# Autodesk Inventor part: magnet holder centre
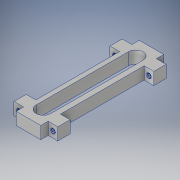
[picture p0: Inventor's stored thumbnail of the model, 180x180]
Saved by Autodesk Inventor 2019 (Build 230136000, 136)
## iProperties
Created: 2019-05
Part Number: magnet holder centre
Material: Aluminum 6061
Document SubType Name: Modeling
Designer: Chloe
Density: 2.7 g/cm^3
Appearance: Aluminum - Flat
Author: Chloe
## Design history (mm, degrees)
sketch "Sketch1"
  geometry: L1 (0, 0)-(-20, 0); L2 (-20, 0)-(-20, -100); L3 (-20, -100)-(0, -100); L4 (0, -100)-(0, 0); L5 (0, -6)-(7.831, -6); L6 (7.831, -6)-(7.831, -16); L7 (7.831, -16)-(0, -16); L8 (0, -16)-(0, -6); L9 (-20, -6)-(-27.831, -6); L10 (-27.831, -6)-(-27.831, -16); L11 (-27.831, -16)-(-20, -16); L12 (-20, -16)-(-20, -6); L13 (-20, -84)-(-27.831, -84); L14 (-27.831, -84)-(-27.831, -94); L15 (-27.831, -94)-(-20, -94); L16 (-20, -94)-(-20, -84); L17 (0, -84)-(7.831, -84); L18 (7.831, -84)-(7.831, -94); L19 (7.831, -94)-(0, -94); L20 (0, -94)-(0, -84)
  constraints: 40 end point, 10 parallel, 5 horizontal, 5 perpendicular, 3 point on line
  dimensions: "d0" = 20 distance of L3.end L2.end; "d1" = 100 distance of L2.end L1.end; "d2" = 7.83128 distance between parallel lines of L6 L8; "d4" = 7.83128 distance between parallel lines of L14 L16 (= d2); "d5" = 7.83128 distance between parallel lines of L12 L10 (= d2); "d6" = 7.83128 distance between parallel lines of L18 L20 (= d2); "d7" = 0 distance between parallel lines of L2 L12; "d8" = 0 distance between parallel lines of L2 L16 (computed from d7); "d9" = 6 distance between parallel lines of L1 L5; "d10" = 6 distance between parallel lines of L3 L19 (= d9); "d11" = 6 distance between parallel lines of L15 L3 (= d9); "d12" = 10 distance between parallel lines of L7 L5; "d13" = 10 distance between parallel lines of L19 L17 (= d12); "d14" = 10 distance between parallel lines of L15 L13 (= d12); "d15" = 10 distance between parallel lines of L9 L11 (derived); "d16" = 6 distance between parallel lines of L1 L9 (derived)
extrude "Extrusion1" new body sketch "Sketch1" distance "d17" = 10; taper "d18" = 0 deg
sketch "Sketch2"
  geometry: L1 (9.65, 12.5)-(9.65, 87.5); L2 (15.65, 12.5)-(15.65, 87.5); L3 (3.65, 87.5)-(3.65, 12.5); L4 (9.65, 12.5)-(84.65, 12.5); L5 (0, 0)-(20, 0) reference; L6 (20, 100)-(0, 100) reference; A1 r 6 centre (9.65, 12.5) between (3.65, 12.5) and (15.65, 12.5); A2 r 6 centre (9.65, 87.5) between (15.65, 87.5) and (3.65, 87.5); 1 further point
  constraints: 10 end point, 4 point on circle, 4 tangent, 2 centre point, 1 horizontal, 1 midpoint, 1 parallel, 1 perpendicular, 1 vertical
  dimensions: "d19" = 75 distance of L1.start L1.end; "d20" = 90 deg angle of L4 L1 (derived); "d21" = 12 diameter of A2; "d22" = 50 distance from line of L5 point (9.65, 50) (= 0.5 x d23); "d23" = 100 distance between parallel lines of L6 L5 (derived)
extrude "Extrusion2" cut sketch "Sketch2" extent not by distance; stored distance "d24" = 10; taper "d25" = 0 deg
sketch "Sketch3"
  geometry: L1 (7.831, 0)-(0, 0) reference; L2 (-27.831, 0)-(-20, 0) reference; L3 (7.831, 0)-(7.831, 10) reference; L4 (-27.831, 0)-(-27.831, 10) reference; 2 further points
  dimensions: "d26" = 5 distance from line of L1 point (3.831, 5); "d27" = 5 distance from line of L2 point (-23.831, 5) (= d26); "d28" = 4 distance from line of L3 point (3.831, 5); "d29" = 4 distance from line of point (-23.831, 5) L4 (= d28)
hole "Hole1" sketch "Sketch3" at (-23.831, 5), (3.831, 5) diameter "d30" = 4; stored, may be unused: countersink angle "d34" = 82 deg, drill point angle "d36" = 118 deg; dims "d31" = 100, "d32" = 9.525, "d33" = 6.35, "d35" = 11.811
thread "Thread8" dims "d51" = 25.4, "d52" = 0
thread "Thread9" dims "d53" = 25.4, "d54" = 0
thread "Thread11" dims "d57" = 25.4, "d58" = 0
thread "Thread12" dims "d59" = 25.4, "d60" = 0
sketch "Sketch5"
  geometry: L1 (2, 0)-(2, 10); L2 (2, 10)-(1.481, 10); L3 (1.481, 10)-(1.481, 0); L4 (1.481, 0)-(2, 0); L5 (0, -104)-(0, 36) reference
  constraints: 8 end point
revolve "Revolution1" sketch "Sketch5" stored, may be unused: angle "d70" = 0 deg
sketch "Sketch4"
  geometry: L1 (-0.408, -0.036)-(-0.35, -0.036); L2 (0.058, -0.484)-(0, -0.596); L3 (-0.7, -0.596)-(-0.758, -0.484); L4 (-0.292, -0.036)-(-0.35, 0.076); L5 (-0.35, 0.076)-(-0.408, -0.036); L6 (-0.7, -0.596)-(-0.642, -0.484); L7 (-0.292, -0.036)-(-0.058, -0.484); L8 (-0.758, -0.484)-(-0.642, -0.484); L9 (0.058, -0.484)-(-0.058, -0.484); L10 (-0.7, -0.596)-(-0.7, -0.484); L11 (0, -0.596)-(0, -0.484); L12 (-0.35, 0.076)-(-0.35, 0); L13 (-0.7, -0.519)-(0, -0.519); L14 (-0.058, -0.484)-(0, -0.596); L15 (-0.642, -0.484)-(-0.408, -0.036); L16 (0, 0)-(0, 0.018); L17 (0, 0.018)-(0, 0); L18 (0, 0)-(0.033, 0); L19 (-0.35, 0)-(-0.35, -0.036); L20 (-0.35, -0.036)-(-0.292, -0.036); A1 r 0.066 centre (-0.7, -0.453) between (-0.758, -0.484) and (-0.7, -0.519); A2 r 0.066 centre (-0.7, -0.453) between (-0.7, -0.519) and (-0.642, -0.484); A3 r 0.066 centre (0, -0.453) between (-0.058, -0.484) and (0, -0.519); A4 r 0.066 centre (0, -0.453) between (0, -0.519) and (0.058, -0.484); A5 r 0.066 centre (-0.35, -0.066) between (-0.35, 0) and (-0.408, -0.036); A6 r 0.066 centre (-0.35, -0.066) between (-0.292, -0.036) and (-0.35, 0)
  constraints: 40 end point, 12 point on circle, 10 parallel, 8 tangent, 6 centre point, 6 collinear, 2 midpoint, 2 point on line, 1 horizontal, 1 perpendicular, 3 other
  dimensions: "d61" = 55 deg angle of L7 L15 (= d68); "d62" = 0.11206 distance of L4.end L1.end (= 0.160083 x Sketch4_Pitch); "d63" = 0.11206 distance of L2.end L11.end (= 0.160083 x Sketch4_Pitch); "Sketch4_ThreadOffset" = 0 distance between parallel lines of L16 L11; "Sketch4_MajorRadius" = 0.51902 distance from line of L13 L16.start; "d66" = 0.7 distance from line of L2.end L10 (= Sketch4_Pitch); "Sketch4_MinorRadius" = 0 distance edge to line of A6 L18 (derived)
coil "Coil1" sketch "Sketch4" pitch "d71" = 0.7007; turns "d73" = 1; dims "d72" = 11.4, "d74" = 0, angle "d75" = 0 deg, angle "d76" = 0 deg, "d77" = 0, "d78" = 0
sketch "Sketch7"
  geometry: L1 (2, 0)-(2, 10); L2 (2, 10)-(1.481, 10); L3 (1.481, 10)-(1.481, 0); L4 (1.481, 0)-(2, 0); L5 (0, -104)-(0, 36) reference
  constraints: 8 end point
revolve "Revolution2" sketch "Sketch7" stored, may be unused: angle "d88" = 0 deg
sketch "Sketch6"
  geometry: L1 (-0.408, -0.036)-(-0.35, -0.036); L2 (0.058, -0.484)-(0, -0.596); L3 (-0.7, -0.596)-(-0.758, -0.484); L4 (-0.292, -0.036)-(-0.35, 0.076); L5 (-0.35, 0.076)-(-0.408, -0.036); L6 (-0.7, -0.596)-(-0.642, -0.484); L7 (-0.292, -0.036)-(-0.058, -0.484); L8 (-0.758, -0.484)-(-0.642, -0.484); L9 (0.058, -0.484)-(-0.058, -0.484); L10 (-0.7, -0.596)-(-0.7, -0.484); L11 (0, -0.596)-(0, -0.484); L12 (-0.35, 0.076)-(-0.35, 0); L13 (-0.7, -0.519)-(0, -0.519); L14 (-0.058, -0.484)-(0, -0.596); L15 (-0.642, -0.484)-(-0.408, -0.036); L16 (0, 0)-(0, 0.018); L17 (0, 0.018)-(0, 0); L18 (0, 0)-(0.033, 0); L19 (-0.35, 0)-(-0.35, -0.036); L20 (-0.35, -0.036)-(-0.292, -0.036); A1 r 0.066 centre (-0.7, -0.453) between (-0.758, -0.484) and (-0.7, -0.519); A2 r 0.066 centre (-0.7, -0.453) between (-0.7, -0.519) and (-0.642, -0.484); A3 r 0.066 centre (0, -0.453) between (-0.058, -0.484) and (0, -0.519); A4 r 0.066 centre (0, -0.453) between (0, -0.519) and (0.058, -0.484); A5 r 0.066 centre (-0.35, -0.066) between (-0.35, 0) and (-0.408, -0.036); A6 r 0.066 centre (-0.35, -0.066) between (-0.292, -0.036) and (-0.35, 0)
  constraints: 40 end point, 12 point on circle, 10 parallel, 8 tangent, 6 centre point, 6 collinear, 2 midpoint, 2 point on line, 1 horizontal, 1 perpendicular, 3 other
  dimensions: "d79" = 55 deg angle of L7 L15 (= d86); "d80" = 0.11206 distance of L4.end L1.end (= 0.160083 x Sketch6_Pitch); "d81" = 0.11206 distance of L2.end L11.end (= 0.160083 x Sketch6_Pitch); "Sketch6_ThreadOffset" = 0 distance between parallel lines of L16 L11; "Sketch6_MajorRadius" = 0.51902 distance from line of L13 L16.start; "d84" = 0.7 distance from line of L2.end L10 (= Sketch6_Pitch); "Sketch6_MinorRadius" = 0 distance edge to line of A6 L18 (derived)
coil "Coil2" sketch "Sketch6" pitch "d89" = 0.7007; turns "d91" = 1; dims "d90" = 11.4, "d92" = 0, angle "d93" = 0 deg, angle "d94" = 0 deg, "d95" = 0, "d96" = 0
sketch "Sketch9"
  geometry: L1 (2, 0)-(2, 10); L2 (2, 10)-(1.481, 10); L3 (1.481, 10)-(1.481, 0); L4 (1.481, 0)-(2, 0); L5 (0, -26)-(0, 114) reference
  constraints: 8 end point
revolve "Revolution3" sketch "Sketch9" stored, may be unused: angle "d106" = 0 deg
sketch "Sketch8"
  geometry: L1 (-0.408, -0.036)-(-0.35, -0.036); L2 (0.058, -0.484)-(0, -0.596); L3 (-0.7, -0.596)-(-0.758, -0.484); L4 (-0.292, -0.036)-(-0.35, 0.076); L5 (-0.35, 0.076)-(-0.408, -0.036); L6 (-0.7, -0.596)-(-0.642, -0.484); L7 (-0.292, -0.036)-(-0.058, -0.484); L8 (-0.758, -0.484)-(-0.642, -0.484); L9 (0.058, -0.484)-(-0.058, -0.484); L10 (-0.7, -0.596)-(-0.7, -0.484); L11 (0, -0.596)-(0, -0.484); L12 (-0.35, 0.076)-(-0.35, 0); L13 (-0.7, -0.519)-(0, -0.519); L14 (-0.058, -0.484)-(0, -0.596); L15 (-0.642, -0.484)-(-0.408, -0.036); L16 (0, 0)-(0, 0.018); L17 (0, 0.018)-(0, 0); L18 (0, 0)-(0.033, 0); L19 (-0.35, 0)-(-0.35, -0.036); L20 (-0.35, -0.036)-(-0.292, -0.036); A1 r 0.066 centre (-0.7, -0.453) between (-0.758, -0.484) and (-0.7, -0.519); A2 r 0.066 centre (-0.7, -0.453) between (-0.7, -0.519) and (-0.642, -0.484); A3 r 0.066 centre (0, -0.453) between (-0.058, -0.484) and (0, -0.519); A4 r 0.066 centre (0, -0.453) between (0, -0.519) and (0.058, -0.484); A5 r 0.066 centre (-0.35, -0.066) between (-0.35, 0) and (-0.408, -0.036); A6 r 0.066 centre (-0.35, -0.066) between (-0.292, -0.036) and (-0.35, 0)
  constraints: 40 end point, 12 point on circle, 10 parallel, 8 tangent, 6 centre point, 6 collinear, 2 midpoint, 2 point on line, 1 horizontal, 1 perpendicular, 3 other
  dimensions: "d97" = 55 deg angle of L7 L15 (= d104); "d98" = 0.11206 distance of L4.end L1.end (= 0.160083 x Sketch8_Pitch); "d99" = 0.11206 distance of L2.end L11.end (= 0.160083 x Sketch8_Pitch); "Sketch8_ThreadOffset" = 0 distance between parallel lines of L16 L11; "Sketch8_MajorRadius" = 0.51902 distance from line of L13 L16.start; "d102" = 0.7 distance from line of L2.end L10 (= Sketch8_Pitch); "Sketch8_MinorRadius" = 0 distance edge to line of A6 L18 (derived)
coil "Coil3" sketch "Sketch8" pitch "d107" = 0.7007; turns "d109" = 1; dims "d108" = 11.4, "d110" = 0, angle "d111" = 0 deg, angle "d112" = 0 deg, "d113" = 0, "d114" = 0
sketch "Sketch11"
  geometry: L1 (2, 0)-(2, 10); L2 (2, 10)-(1.481, 10); L3 (1.481, 10)-(1.481, 0); L4 (1.481, 0)-(2, 0); L5 (0, -26)-(0, 114) reference
  constraints: 8 end point
revolve "Revolution4" sketch "Sketch11" stored, may be unused: angle "d124" = 0 deg
sketch "Sketch10"
  geometry: L1 (-0.408, -0.036)-(-0.35, -0.036); L2 (0.058, -0.484)-(0, -0.596); L3 (-0.7, -0.596)-(-0.758, -0.484); L4 (-0.292, -0.036)-(-0.35, 0.076); L5 (-0.35, 0.076)-(-0.408, -0.036); L6 (-0.7, -0.596)-(-0.642, -0.484); L7 (-0.292, -0.036)-(-0.058, -0.484); L8 (-0.758, -0.484)-(-0.642, -0.484); L9 (0.058, -0.484)-(-0.058, -0.484); L10 (-0.7, -0.596)-(-0.7, -0.484); L11 (0, -0.596)-(0, -0.484); L12 (-0.35, 0.076)-(-0.35, 0); L13 (-0.7, -0.519)-(0, -0.519); L14 (-0.058, -0.484)-(0, -0.596); L15 (-0.642, -0.484)-(-0.408, -0.036); L16 (0, 0)-(0, 0.018); L17 (0, 0.018)-(0, 0); L18 (0, 0)-(0.033, 0); L19 (-0.35, 0)-(-0.35, -0.036); L20 (-0.35, -0.036)-(-0.292, -0.036); A1 r 0.066 centre (-0.7, -0.453) between (-0.758, -0.484) and (-0.7, -0.519); A2 r 0.066 centre (-0.7, -0.453) between (-0.7, -0.519) and (-0.642, -0.484); A3 r 0.066 centre (0, -0.453) between (-0.058, -0.484) and (0, -0.519); A4 r 0.066 centre (0, -0.453) between (0, -0.519) and (0.058, -0.484); A5 r 0.066 centre (-0.35, -0.066) between (-0.35, 0) and (-0.408, -0.036); A6 r 0.066 centre (-0.35, -0.066) between (-0.292, -0.036) and (-0.35, 0)
  constraints: 40 end point, 12 point on circle, 10 parallel, 8 tangent, 6 centre point, 6 collinear, 2 midpoint, 2 point on line, 1 horizontal, 1 perpendicular, 3 other
  dimensions: "d115" = 55 deg angle of L7 L15 (= d122); "d116" = 0.11206 distance of L4.end L1.end (= 0.160083 x Sketch10_Pitch); "d117" = 0.11206 distance of L2.end L11.end (= 0.160083 x Sketch10_Pitch); "Sketch10_ThreadOffset" = 0 distance between parallel lines of L16 L11; "Sketch10_MajorRadius" = 0.51902 distance from line of L13 L16.start; "d120" = 0.7 distance from line of L2.end L10 (= Sketch10_Pitch); "Sketch10_MinorRadius" = 0 distance edge to line of A6 L18 (derived)
coil "Coil4" sketch "Sketch10" pitch "d125" = 0.7007; turns "d127" = 1; dims "d126" = 11.4, "d128" = 0, angle "d129" = 0 deg, angle "d130" = 0 deg, "d131" = 0, "d132" = 0
body "Solid1"
body "Solid2"
body "Solid3"
body "Solid4"
body "Solid5"
other parameters: "d68" = 55 deg [user parameter; used in 1 equation term], "Sketch4_Pitch" = 0.7 [user parameter; used in 3 equation terms], "d86" = 55 deg [user parameter; used in 1 equation term], "Sketch6_Pitch" = 0.7 [user parameter; used in 3 equation terms], "d104" = 55 deg [user parameter; used in 1 equation term], "Sketch8_Pitch" = 0.7 [user parameter; used in 3 equation terms], "d122" = 55 deg [user parameter; used in 1 equation term], "Sketch10_Pitch" = 0.7 [user parameter; used in 3 equation terms]
